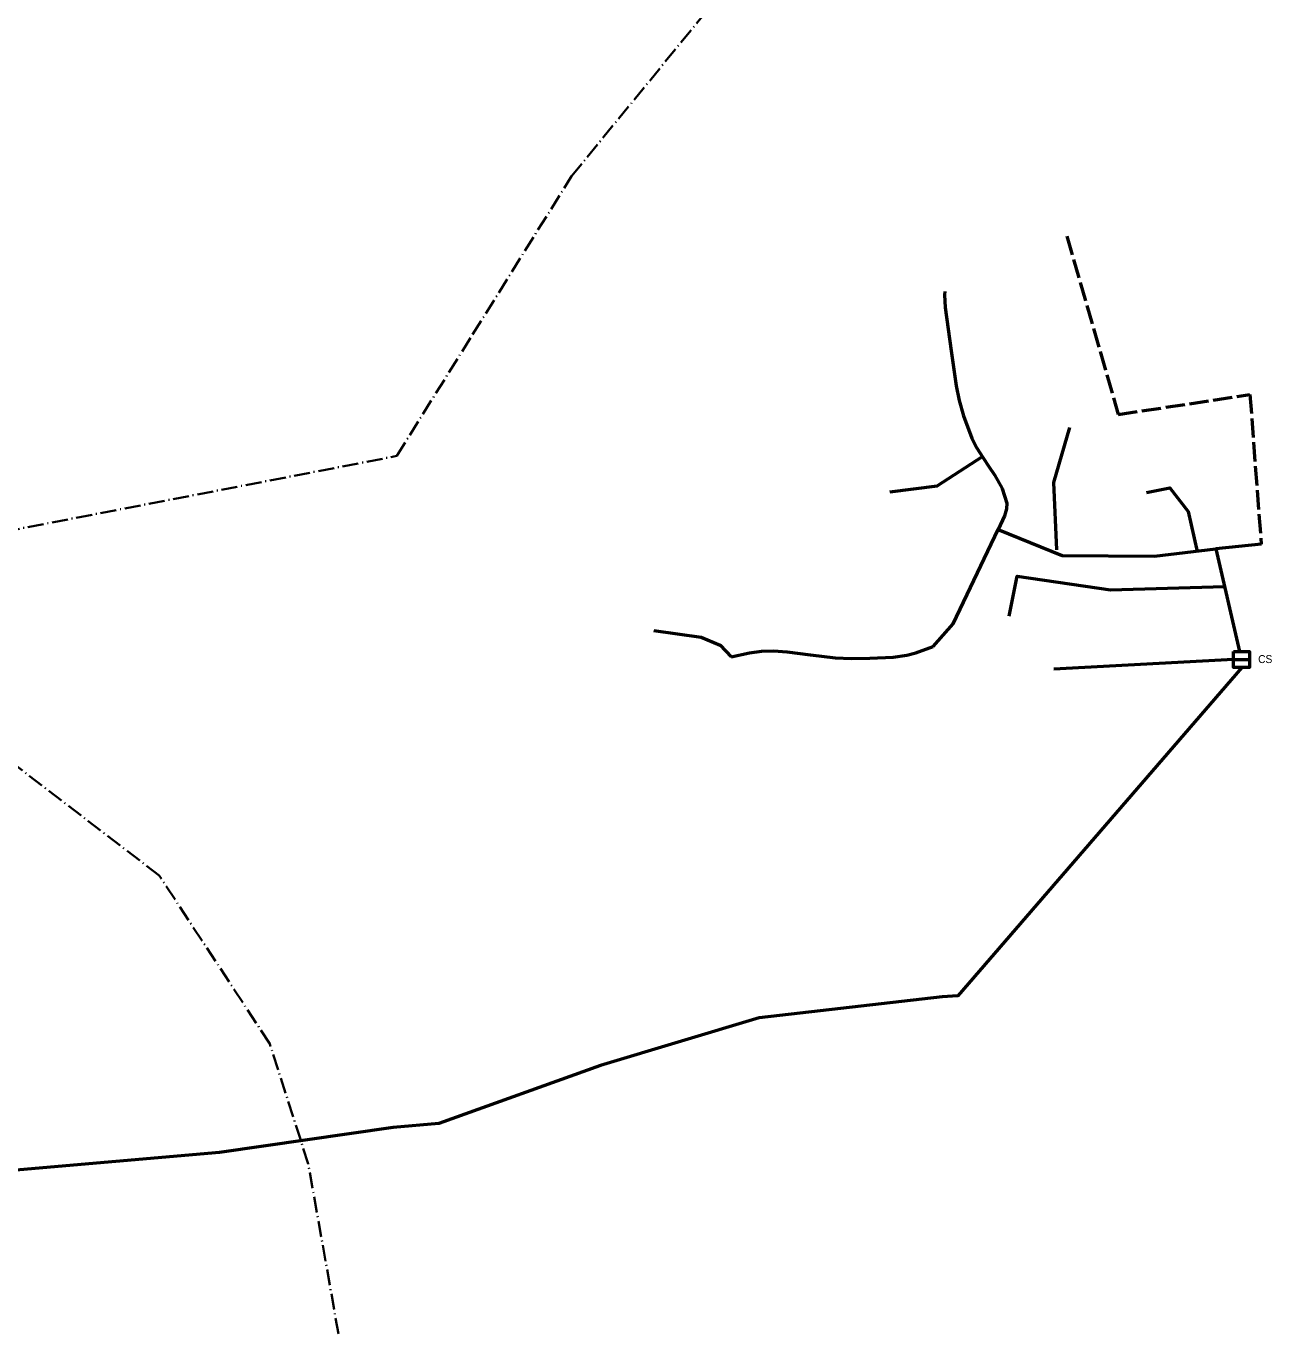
# Model space of a CAD drawing. Extents: x -650270 to -643402, y -1075206 to -1066724.
# Drawn here: x -644959 to -643402, y -1070961 to -1069326 of the extents above; entities that cross this region are included whole.
import ezdxf

# ---------------------------------------------------------------- set-up
doc = ezdxf.new("R2010")
doc.units = 0
doc.header["$LTSCALE"] = 4
doc.linetypes.add('DOT_DASHED', pattern=[7.7, 5, -1.2, 0.3, -1.2])
doc.linetypes.add('LONG_DASHED', pattern=[7.5, 6, -1.5])
for name, color, linetype, lineweight in [('17', 7, 'DOT_DASHED', 35), ('41', 7, 'Continuous', 25), ('48', 7, 'Continuous', 53), ('50', 7, 'Continuous', 53)]:
    doc.layers.add(name, color=color, linetype=linetype, lineweight=lineweight)
doc.layers.add('42', color=7, linetype='Continuous')

msp = doc.modelspace()

# ---------------------------------------------------------------- linework, layer by layer
at = {"layer": '17'}
for points in [[(-644568.435, -1070960.552), (-644606.234, -1070747.935), (-644654.246, -1070597.895), (-644792.283, -1070387.84), (-645046.599, -1070192.79), (-645228.623, -1070004.752), (-645232.28, -1069980.924), (-645262.713, -1069836.388), (-645315.002, -1069657.333), (-645409.031, -1069473.75), (-645471.738, -1069397.026), (-645547.224, -1069323.801), (-645594.94, -1069288.511), (-645620.197, -1069220.915), (-645784.301, -1069029.743), (-645967.439, -1068809.81), (-646082.481, -1068583.109), (-646148.037, -1068369.943), (-646184.835, -1068097.563), (-646183.288, -1067867.427)], [(-645228.623, -1070004.752), (-644495.665, -1069863.346), (-644400.764, -1069711.504), (-644277.073, -1069513.597), (-644078.1, -1069270.213), (-644047.301, -1069043.419)]]:
    msp.add_lwpolyline(points, dxfattribs=at)
at = {"layer": '41', "lineweight": 53}
msp.add_line((-643450.027, -1070117.812), (-643430.027, -1070117.812), dxfattribs=at)
msp.add_lwpolyline([(-643450.027, -1070107.812), (-643430.027, -1070107.812), (-643430.027, -1070127.812), (-643450.027, -1070127.812)], close=True, dxfattribs=at)
at = {"layer": '48', "linetype": 'LONG_DASHED'}
msp.add_line((-643658.395, -1069588.818), (-643594.181, -1069811.599), dxfattribs=at)
at = {"layer": '48'}
for p, q in [((-643415.602, -1069973.457), (-643472.434, -1069979.54)), ((-643674.528, -1070129.34), (-643450.027, -1070117.352))]:
    msp.add_line(p, q, dxfattribs=at)
for points in [[(-643810.627, -1069657.665), (-643811.385, -1069662.021), (-643810.389, -1069677.722), (-643802.82, -1069731.886), (-643796.749, -1069775.852), (-643792.823, -1069793.926), (-643787.529, -1069813.369), (-643777.123, -1069840.937), (-643771.098, -1069852.895), (-643763.019, -1069865.538), (-643755.762, -1069876.675), (-643748.825, -1069886.853), (-643739.057, -1069904.105), (-643733.398, -1069922.453), (-643733.672, -1069929.3), (-643736.136, -1069938.154), (-643744.205, -1069955.268)], [(-643655.213, -1069827.906), (-643674.851, -1069896.398), (-643671.436, -1069980.856)], [(-643879.717, -1069908.04), (-643820.566, -1069900.574), (-643763.713, -1069863.82)], [(-643558.728, -1069909.08), (-643529.51, -1069903.099), (-643506.883, -1069932.918), (-643495.544, -1069982.565)], [(-643825.501, -1070101.354), (-643800.43, -1070073.069), (-643744.205, -1069955.268)], [(-643744.205, -1069955.268), (-643664.391, -1069987.784), (-643548.771, -1069988.527), (-643472.434, -1069979.54), (-643442.585, -1070107.812)], [(-643730.467, -1070063.614), (-643720.412, -1070013.703), (-643603.827, -1070030.469), (-643461.54, -1070026.354)], [(-644174.372, -1070081.528), (-644115.344, -1070090.018), (-644091.49, -1070099.721), (-644077.983, -1070114.354)], [(-644077.983, -1070114.354), (-644054.663, -1070109.432), (-644040.027, -1070107.201), (-644024.686, -1070106.729), (-644007.981, -1070107.962), (-643978.816, -1070112.024), (-643947.688, -1070115.858), (-643927.411, -1070116.568), (-643904.548, -1070116.112), (-643875.543, -1070114.925), (-643858.108, -1070112.46), (-643846.88, -1070109.266), (-643825.501, -1070101.354)]]:
    msp.add_lwpolyline(points, dxfattribs=at)
at = {"layer": '48', "linetype": 'LONG_DASHED'}
msp.add_lwpolyline([(-643594.181, -1069811.599), (-643429.636, -1069786.459), (-643415.602, -1069973.457)], dxfattribs=at)
at = {"layer": '50'}
msp.add_lwpolyline([(-643439.868, -1070127.812), (-643794.576, -1070538.041), (-643814.314, -1070539.274), (-644042.664, -1070565.642), (-644241.161, -1070625.072), (-644443.224, -1070697.577), (-644500.038, -1070702.585), (-644716.965, -1070734.034), (-644976.129, -1070756.486), (-645086.887, -1070754.876), (-645202.78, -1070753.267), (-645305.795, -1070754.34), (-645369.783, -1070785.657), (-645445.374, -1070804.496)], dxfattribs=at)

# ---------------------------------------------------------------- texts
at = {"layer": '42', "width": 0.95}
msp.add_text('CS', height=10, dxfattribs=at).set_placement((-643419.321, -1070122.194))

doc.saveas('drawing.dxf')
